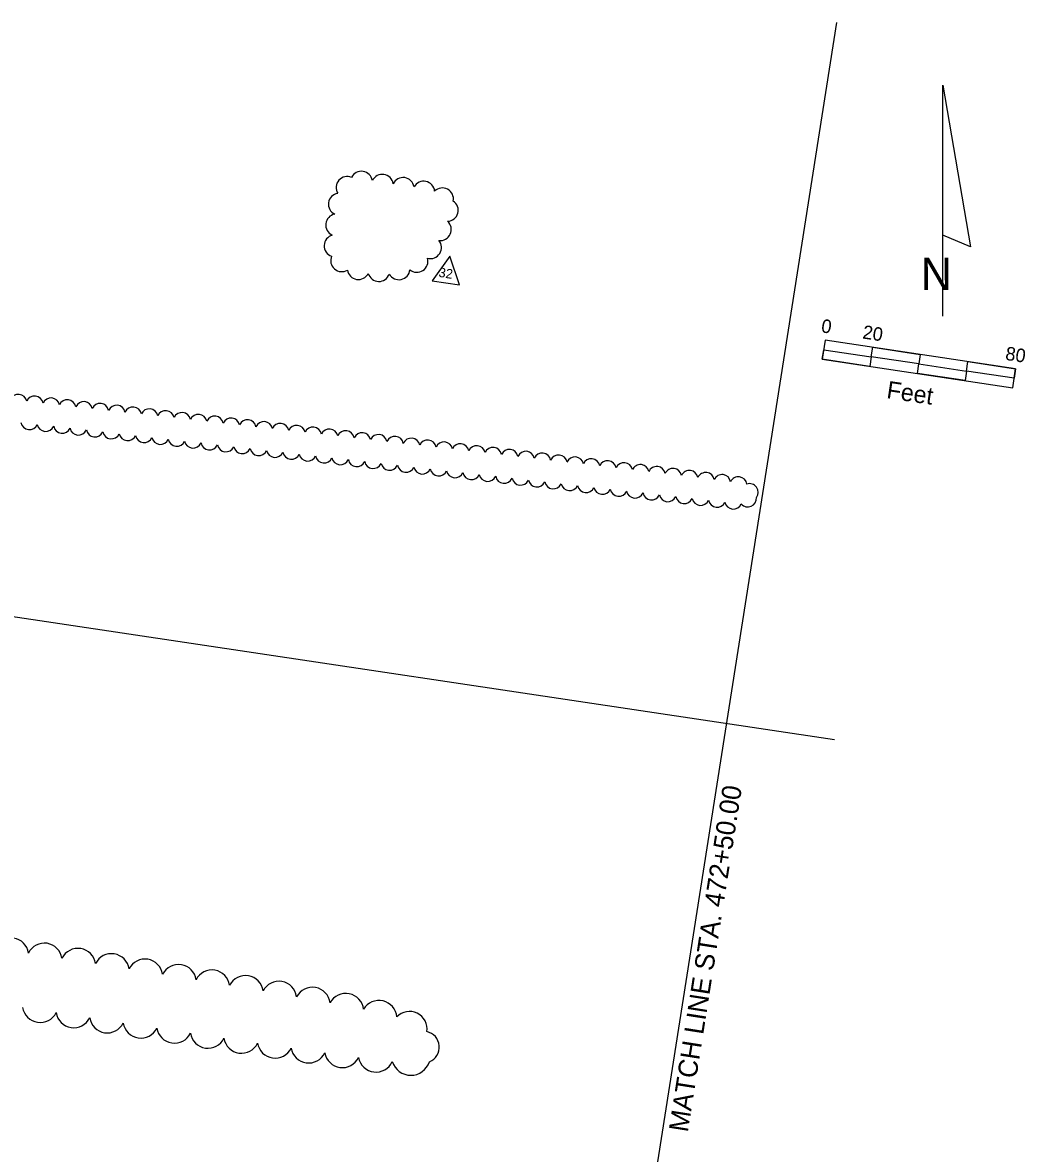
# Model space of a CAD drawing. Extents: x 924436 to 925782, y 636346 to 637319.
# Drawn here: x 925365.1 to 925781.7, y 636692.2 to 637161.7 of the extents above; entities that cross this region are included whole.
import ezdxf

# ---------------------------------------------------------------- set-up
doc = ezdxf.new("R2010")
doc.units = 0
for name, color, linetype in [('ActivePointCell_dp', 7, 'Continuous'), ('Cloud_dp', 7, 'Continuous'), ('MatchLines_dp', 7, 'Continuous'), ('NorthArw_dp', 7, 'Continuous'), ('Scale_dp', 7, 'Continuous')]:
    doc.layers.add(name, color=color, linetype=linetype)

msp = doc.modelspace()

# ---------------------------------------------------------------- linework, layer by layer
at = {"layer": 'ActivePointCell_dp'}
msp.add_line((924609.88, 637027.58), (925702.36, 636864), dxfattribs=at)
at = {"layer": 'Cloud_dp'}
msp.add_lwpolyline([(925542.57, 637064.67), (925535.21, 637054.52), (925546.63, 637052.81)], close=True, dxfattribs=at)
for centre, radius, start, end in [((925505.84, 637095.4), 4.59, 8.9841, 153.9841), ((925499.88, 637093.21), 4.59, 66.3605, 211.3605), ((925514.49, 637094.1), 4.59, 8.9841, 153.9841), ((925523.14, 637092.8), 4.59, 8.8934, 153.8934), ((925531.68, 637091.27), 4.59, 5.8052, 150.8052), ((925496.71, 637086.29), 4.59, 99.3198, 244.3198), ((925539.46, 637088.46), 4.59, 349.512, 134.512), ((925541.47, 637083.78), 4.58, 272.0182, 57.0182), ((925495.58, 637077.66), 4.59, 100.826, 245.826), ((925538.56, 637075.8), 4.59, 262.9465, 47.9465), ((925494.95, 637069.06), 4.59, 105.8096, 250.8096), ((925534.48, 637068.3), 4.59, 254.8957, 39.8957), ((925497.64, 637062.88), 4.59, 156.2267, 301.2267), ((925528.87, 637062.63), 4.59, 230.7481, 15.7481), ((925504.56, 637059.63), 4.59, 188.3737, 333.3737), ((925521.41, 637059.55), 4.59, 209.1035, 354.1035), ((925513.07, 637058.82), 4.59, 195.8621, 340.8621), ((925363.26, 637003.78), 3.59, 11.182, 156.182), ((925370.06, 637003.03), 3.59, 11.1789, 156.1789), ((925376.87, 637002.28), 3.59, 11.1756, 156.1756), ((925383.67, 637001.52), 3.59, 11.1722, 156.1722), ((925390.47, 637000.77), 3.59, 11.1686, 156.1686), ((925397.27, 637000.01), 3.59, 11.165, 156.165), ((925404.08, 636999.26), 3.59, 11.1612, 156.1612), ((925410.88, 636998.5), 3.59, 11.1572, 156.1572), ((925417.68, 636997.74), 3.59, 11.1531, 156.1531), ((925424.48, 636996.99), 3.59, 11.1488, 156.1488), ((925431.28, 636996.23), 3.59, 11.1443, 156.1443), ((925438.09, 636995.47), 3.59, 11.1397, 156.1397), ((925444.89, 636994.71), 3.59, 11.1348, 156.1348), ((925451.69, 636993.96), 3.59, 11.1297, 156.1297), ((925458.49, 636993.2), 3.59, 11.1244, 156.1244), ((925367.9, 636996.32), 3.59, 191.0304, 336.0304), ((925374.7, 636995.55), 3.59, 191.0309, 336.0309), ((925381.5, 636994.78), 3.59, 191.0314, 336.0314), ((925388.3, 636994.01), 3.59, 191.0319, 336.0319), ((925395.1, 636993.24), 3.59, 191.0324, 336.0324), ((925465.29, 636992.44), 3.59, 11.1187, 156.1187), ((925472.09, 636991.67), 3.59, 11.1128, 156.1128), ((925478.89, 636990.91), 3.59, 11.1066, 156.1066), ((925485.7, 636990.15), 3.59, 11.1001, 156.1001), ((925492.5, 636989.39), 3.59, 11.0931, 156.0931), ((925499.3, 636988.62), 3.59, 11.0858, 156.0858), ((925401.91, 636992.47), 3.59, 191.0329, 336.0329), ((925408.71, 636991.7), 3.59, 191.0335, 336.0335), ((925415.51, 636990.93), 3.59, 191.0341, 336.0341), ((925422.31, 636990.16), 3.59, 191.0347, 336.0347), ((925429.11, 636989.39), 3.59, 191.0353, 336.0353), ((925435.91, 636988.62), 3.59, 191.036, 336.036), ((925442.71, 636987.85), 3.59, 191.0367, 336.0367), ((925506.1, 636987.86), 3.59, 11.078, 156.078), ((925512.9, 636987.09), 3.59, 11.0697, 156.0697), ((925519.7, 636986.32), 3.59, 11.0608, 156.0608), ((925526.5, 636985.56), 3.59, 11.0513, 156.0513), ((925533.3, 636984.79), 3.59, 11.0411, 156.0411), ((925540.1, 636984.02), 3.59, 11.0301, 156.0301), ((925449.51, 636987.07), 3.59, 191.0374, 336.0374), ((925456.31, 636986.3), 3.59, 191.0382, 336.0382), ((925463.11, 636985.53), 3.59, 191.039, 336.039), ((925469.91, 636984.76), 3.59, 191.0398, 336.0398), ((925476.71, 636983.99), 3.59, 191.0407, 336.0407), ((925483.51, 636983.22), 3.59, 191.0416, 336.0416), ((925546.9, 636983.24), 3.59, 11.0182, 156.0182), ((925553.7, 636982.47), 3.59, 11.0052, 156.0052), ((925560.5, 636981.7), 3.59, 10.9911, 155.9911), ((925567.3, 636980.92), 3.59, 10.9755, 155.9755), ((925574.1, 636980.14), 3.59, 10.9583, 155.9583), ((925580.9, 636979.36), 3.59, 10.9391, 155.9391), ((925490.31, 636982.45), 3.59, 191.0426, 336.0426), ((925497.11, 636981.69), 3.59, 191.0436, 336.0436), ((925503.91, 636980.92), 3.59, 191.0447, 336.0447), ((925510.71, 636980.15), 3.59, 191.0459, 336.0459), ((925517.51, 636979.38), 3.59, 191.0471, 336.0471), ((925524.32, 636978.61), 3.59, 191.0485, 336.0485), ((925587.7, 636978.58), 3.59, 10.9176, 155.9176), ((925594.5, 636977.79), 3.59, 10.8931, 155.8931), ((925601.29, 636977), 3.59, 10.8651, 155.8651), ((925608.09, 636976.21), 3.59, 10.8325, 155.8325), ((925614.89, 636975.41), 3.59, 10.7938, 155.7938), ((925621.69, 636974.61), 3.59, 10.747, 155.747), ((925531.12, 636977.84), 3.59, 191.0499, 336.0499), ((925537.92, 636977.07), 3.59, 191.0515, 336.0515), ((925544.72, 636976.3), 3.59, 191.0531, 336.0531), ((925551.52, 636975.53), 3.59, 191.0549, 336.0549), ((925558.32, 636974.77), 3.59, 191.0569, 336.0569), ((925565.12, 636974), 3.59, 191.0591, 336.0591), ((925628.48, 636973.8), 3.59, 10.6888, 155.6888), ((925635.27, 636972.99), 3.59, 10.6135, 155.6135), ((925642.07, 636972.16), 3.59, 10.5108, 155.5108), ((925648.86, 636971.32), 3.59, 10.3583, 155.3583), ((925655.64, 636970.45), 3.59, 10.0949, 155.0949), ((925662.41, 636969.53), 3.59, 9.4263, 154.4263), ((925571.92, 636973.23), 3.59, 191.0615, 336.0615), ((925578.72, 636972.46), 3.59, 191.0641, 336.0641), ((925585.52, 636971.7), 3.59, 191.0671, 336.0671), ((925592.32, 636970.93), 3.59, 191.0705, 336.0705), ((925599.12, 636970.16), 3.59, 191.0743, 336.0743), ((925605.93, 636969.4), 3.59, 191.0787, 336.0787), ((925667.05, 636966.71), 3.58, 322.9343, 107.9343), ((925612.73, 636968.63), 3.59, 191.084, 336.084), ((925619.53, 636967.87), 3.59, 191.0902, 336.0902), ((925626.33, 636967.1), 3.59, 191.0979, 336.0979), ((925633.13, 636966.34), 3.59, 191.1077, 336.1077), ((925639.93, 636965.58), 3.59, 191.1208, 336.1208), ((925646.73, 636964.82), 3.59, 191.1394, 336.1394), ((925666.34, 636964.2), 3.59, 220.5755, 5.5755), ((925653.53, 636964.06), 3.59, 191.1694, 336.1694), ((925660.34, 636963.31), 3.59, 191.2314, 336.2314), ((925360.18, 636774.26), 7.39, 8.6669, 153.6669), ((925374.11, 636772.09), 7.39, 8.607, 153.607), ((925388.05, 636769.9), 7.4, 8.5381, 153.5381), ((925401.98, 636767.69), 7.4, 8.4577, 153.4577), ((925415.9, 636765.46), 7.4, 8.3624, 153.3624), ((925429.82, 636763.21), 7.4, 8.2466, 153.2466), ((925443.74, 636760.92), 7.4, 8.102, 153.102), ((925457.65, 636758.6), 7.4, 7.914, 152.914), ((925471.55, 636756.22), 7.4, 7.6553, 152.6553), ((925485.45, 636753.75), 7.41, 7.2658, 152.2658), ((925499.35, 636751.15), 7.45, 6.5708, 151.5708), ((925372.38, 636753.89), 7.39, 188.6647, 333.6647), ((925513.15, 636748.24), 7.42, 4.6068, 149.6068), ((925386.31, 636751.73), 7.39, 188.7093, 333.7093), ((925400.25, 636749.58), 7.39, 188.7608, 333.7608), ((925525.81, 636743.82), 7.28, 351.4023, 136.4023), ((925414.19, 636747.44), 7.39, 188.8212, 333.8212), ((925428.14, 636745.33), 7.4, 188.8933, 333.8933), ((925442.08, 636743.23), 7.4, 188.9815, 333.9815), ((925456.03, 636741.15), 7.4, 189.093, 334.093), ((925531.56, 636736.31), 6.59, 292.3378, 77.3378), ((925469.98, 636739.11), 7.4, 189.24, 334.24), ((925483.94, 636737.11), 7.4, 189.4469, 334.4469), ((925497.91, 636735.17), 7.4, 189.7707, 334.7707), ((925511.91, 636733.35), 7.42, 190.3968, 335.3968), ((925526.37, 636732.67), 8.08, 197.3021, 342.3021)]:
    msp.add_arc(centre, radius, start, end, dxfattribs=at)
at = {"layer": 'MatchLines_dp'}
msp.add_line((925703.24, 637161.71), (925589.57, 636439.09), dxfattribs=at)
at = {"layer": 'NorthArw_dp'}
msp.add_line((925747.3, 637039.78), (925747.3, 637135.78), dxfattribs=at)
msp.add_lwpolyline([(925747.3, 637073.38), (925747.3, 637135.78), (925758.82, 637068.58)], close=True, dxfattribs=at)
at = {"layer": 'Scale_dp'}
for p, q in [((925698.44, 637029.84), (925697.26, 637021.93)), ((925777.56, 637018), (925698.44, 637029.84)), ((925697.26, 637021.93), (925776.38, 637010.08)), ((925776.38, 637010.08), (925777.56, 637018))]:
    msp.add_line(p, q, dxfattribs=at)
for points in [[(925697.26, 637021.93), (925697.85, 637025.89), (925717.63, 637022.92), (925717.04, 637018.97)], [(925717.63, 637022.92), (925718.22, 637026.88), (925738, 637023.92), (925737.41, 637019.96)], [(925757.19, 637017), (925757.78, 637020.96), (925777.56, 637018), (925776.97, 637014.04)], [(925736.82, 637016.01), (925737.41, 637019.96), (925757.19, 637017), (925756.6, 637013.05)]]:
    msp.add_lwpolyline(points, close=True, dxfattribs=at)

# ---------------------------------------------------------------- texts
at = {"layer": 'Cloud_dp'}
msp.add_text('32', height=3.938, rotation=351.4841, dxfattribs=at).set_placement((925537.69, 637056.15))
at = {"layer": 'MatchLines_dp'}
msp.add_text('MATCH LINE STA. 472+50.00', height=8, rotation=81.0712, dxfattribs=at).set_placement((925641.4, 636700.69))
at = {"layer": 'NorthArw_dp'}
msp.add_text('N', height=13.43, dxfattribs=at).set_placement((925738.18, 637050.65))
at = {"layer": 'Scale_dp'}
for s, height, p in [('0', 5.6, (925696.58, 637033.15)), ('20', 5.6, (925713.76, 637030.58)), ('80', 5.6, (925773.08, 637021.7)), ('Feet', 7.2, (925723.71, 637005.84))]:
    msp.add_text(s, height=height, rotation=351.4841, dxfattribs=at).set_placement(p)

doc.saveas('drawing.dxf')
